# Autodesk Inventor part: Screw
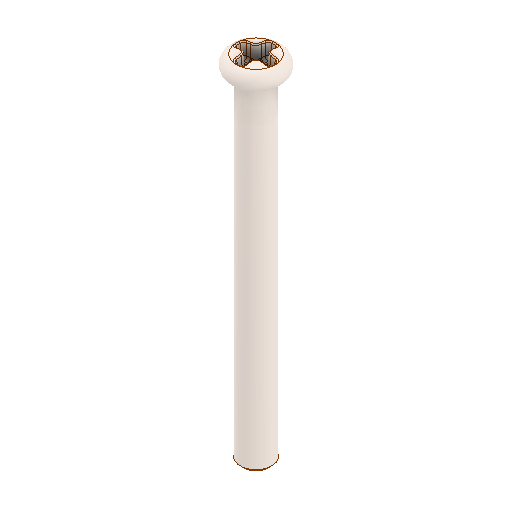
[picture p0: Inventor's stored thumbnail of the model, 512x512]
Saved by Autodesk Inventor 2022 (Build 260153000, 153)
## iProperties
Created: 2020-10
Part Number: Screw
Material: Generico
Document SubType Name: Modeling
Designer: admin
Density: 1 g/cm^3
Appearance: Default
Author: admin
Sending System: SolidWorks 2020
Last Author: Simon
Last Saved: 2020-10-31
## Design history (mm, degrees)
fillet "Fillet4"
node "Solido1"
